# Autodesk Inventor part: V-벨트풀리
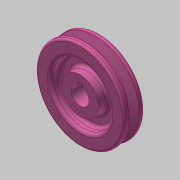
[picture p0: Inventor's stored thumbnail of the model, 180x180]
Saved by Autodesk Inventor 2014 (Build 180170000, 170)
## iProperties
Created: 2018-11
Part Number: V-벨트풀리
Material: 알루미늄 6061
Document SubType Name: Modeling
Designer: mduedu
Density: 1 g/cm^3
Appearance: 분홍색
Author: mduedu
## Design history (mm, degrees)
sketch "스케치1"
  geometry: L1 (-9.5, 0)-(9.5, 0); L2 (9.5, 0)-(9.5, 42.7); L3 (9.5, 42.7)-(-9.5, 42.7); L4 (-9.5, 42.7)-(-9.5, 0); L5 (-4.877, 42.7)-(-1.953, 33.7); L6 (-1.953, 33.7)-(1.953, 33.7); L7 (1.953, 33.7)-(4.877, 42.7); L8 (0, 0)-(0, 42.7); L9 (-9.5, 40)-(9.5, 40); 3 further points
  constraints: 18 end point, 8 point on line, 3 perpendicular, 2 midpoint, 2 parallel, 1 coincident, 1 horizontal, 1 other
  dimensions: "d0" = 85.4 diameter of L3 L1; "d2" = 19 distance of L2.end L3.end; "d3" = 80 diameter of L9 L1; "d4" = 36 deg angle of L7 L5; "d5" = 6.3 distance between parallel lines of L6 L9; "d6" = 8 distance of point (4, 40) point (-4, 40)
revolve "회전1" sketch "스케치1" stored, may be unused: angle "d7" = 90 deg
sketch "스케치2"
  geometry: L1 (-2.5, 8.124)-(2.5, 8.124); L2 (2.5, 8.124)-(2.5, 10.8); L3 (2.5, 10.8)-(-2.5, 10.8); L4 (-2.5, 10.8)-(-2.5, 8.124); A1 r 8.5 centre (0, 0) between (-2.5, 8.124) and (2.5, 8.124); 1 further point
  constraints: 8 end point, 2 parallel, 2 point on circle, 1 centre point, 1 coincident, 1 horizontal, 1 perpendicular
  dimensions: "d8" = 17 diameter of A1; "d10" = 19.3 dimension on A1 L3; "d11" = 5 distance of L2.end L3.end
extrude "돌출1" cut sketch "스케치2" stored distance "d12" = 10; taper "d13" = 0 deg
chamfer "모따기1" distance "d14" = 1; stored, may be unused: second distance "d15" = 2, angle "d16" = 45 deg
fillet "모깎기1" dims "d17" = 1, "d18" = 0.5, "d19" = 2
sketch "스케치3"
  geometry: C1 r 17.5 at (0, 0); C2 r 28.5 at (0, 0); 1 further point
  constraints: 2 centre point, 2 coincident
  dimensions: "d20" = 35 diameter of C1; "d23" = 57 diameter of C2
extrude "돌출2" cut sketch "스케치3" distance "d24" = 9.5; taper "d25" = 0 deg
fillet "모깎기2" dims "d26" = 3
node "솔리드1"
